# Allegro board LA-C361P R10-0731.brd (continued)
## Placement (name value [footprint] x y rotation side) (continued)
CV797  4.7U_0603_6.3V6K  [C_0603]  224.37 59.61 270 top
CV798  4.7U_0603_6.3V6K  [C_0603]  204.6 66.43 180 top
CV799  0.1U_0402_10V7K  [C_0402]  213.25 101.93 0 top
CV800  0.1U_0402_10V7K  [C_0402]  216.07 108.73 270 top
CV801  0.1U_0402_10V7K  [C_0402]  225.87 109.85 90 top
CV802  0.1U_0402_10V7K  [C_0402]  211.15 108.39 180 top
CV803  0.1U_0402_10V7K  [C_0402]  205.14 106.69 0 top
CV804  0.1U_0402_10V7K  [C_0402]  197.99 102.71 90 top
CV805  0.1U_0402_10V7K  [C_0402]  197.66 106.66 0 top
CV806  0.1U_0402_10V7K  [C_0402]  196.52 106.66 180 top
CV807  0.1U_0402_10V7K  [C_0402]  239.09 76.91 180 top
CV808  0.1U_0402_10V7K  [C_0402]  242.46 77.61 180 top
CV809  0.1U_0402_10V7K  [C_0402]  241.56 69.68 270 top
CV810  0.1U_0402_10V7K  [C_0402]  241.56 67.84 270 top
CV811  0.1U_0402_10V7K  [C_0402]  243.73 88.65 180 top
CV812  0.1U_0402_10V7K  [C_0402]  247.21 94.04 90 top
CV813  0.1U_0402_10V7K  [C_0402]  243.16 95.58 180 top
CV814  0.1U_0402_10V7K  [C_0402]  247.21 92.26 90 top
CV815  22U_0603_6.3V6M  [C_0603]  219.08 71.07 0 top
CV816  22U_0603_6.3V6M  [C_0603]  223.46 94.37 0 top
CZ4  470P_0603_50V7K  [C_0603]  310.2 33.66 180 top
CZ6  470P_0603_50V7K  [C_0603]  310.2 35.06 180 top
CZ8  10U_0603_6.3V6M  [C_0603]  307.56 32.39 180 top
CZ9  10U_0603_6.3V6M  [C_0603]  310.74 38.62 0 top
CZ11  1U_0603_10V6K  [C_0603]  55.88 6.42 90 top
CZ12  1U_0603_10V6K  [C_0603]  315.79 35.82 90 top
CZ18  1U_0402_6.3V6K  [C_0402]  58.17 6.98 90 top
CZ19  0.1U_0402_10V7K  [C_0402]  61.41 5.86 270 top
CZ20  2200P_0402_25V7K  [C_0402]  57.07 1.66 180 top
CZ26  1U_0402_6.3V6K  [C_0402]  343.35 44.55 0 bottom
CZ28  0.1U_0402_10V7K  [C_0402]  181.48 80.87 180 top
CZ29  0.1U_0402_10V7K  [C_0402]  339.35 45.3 270 bottom
CZ31  2200P_0402_25V7K  [C_0402]  340.56 43.06 180 bottom
CZ37  470P_0603_50V7K  [C_0603]  240.6 7.18 90 top
CZ39  470P_0603_50V7K  [C_0603]  241.94 7.18 90 top
CZ41  0.1U_0402_10V7K  [C_0402]  46.86 29.3 270 top
CZ43  0.1U_0402_10V7K  [C_0402]  37.85 23.17 90 top
CZ44  1U_0402_6.3V6K  [C_0402]  46.86 25.9 90 top
CZ45  0.1U_0402_10V7K  [C_0402]  237.55 8.28 270 top
CZ46  0.1U_0402_10V7K  [C_0402]  244.86 8.34 270 top
CZ47  0.1U_0402_10V7K  [C_0402]  181.23 82.18 180 bottom
CZ49  0.1U_0402_10V7K  [C_0402]  174.48 66.23 90 top
CZ53  1U_0603_10V6K  [C_0603]  181.1 14.23 90 top
CZ54  1U_0603_10V6K  [C_0603]  180.91 8.2 0 top
CZ57  2200P_0402_25V7K  [C_0402]  131.15 69.13 0 top
CZ82  0.1U_0402_10V7K  [C_0402]  184.72 83.07 270 bottom
CZ86  0.1U_0402_10V7K  [C_0402]  181.31 86.65 270 bottom
CZ88  1U_0402_6.3V6K  [C_0402]  181.23 83.12 180 bottom
CZ95  2200P_0402_25V7K  [C_0402]  228.61 61.35 180 top
CZ96  1U_0402_6.3V6K  [C_0402]  182.22 85.86 0 top
CZ97  0.1U_0402_25V6  [C_0402]  180.59 85.86 180 top
D122  -  [BAS40-04_SOT23-3]  332.8 77.15 90 top
DE2  AZ5125-02S.R7G_SOT23-3  [AZ5125-02SPR7G_SOT23-3]  345.85 110.94 90 top
DE4  -  [PESD5V0U2BT_SOT23-3]  227.59 14.11 90 bottom
DE5  -  [PESD5V0U2BT_SOT23-3]  214.33 13.75 270 top
DE7  -  [RB751S40T1G_SOD523-2]  99.23 35.41 270 top
DE8  -  [RB751S40T1G_SOD523-2]  322.71 40.59 270 top
DE9  -  [TVNST52302AB0_SOT523-3]  12.64 12.58 0 top
DE11  -  [RB751S40T1G_SOD523-2]  309.44 9.28 180 top
DH1  -  [RB751S40T1G_SOD523-2]  90.04 4.33 180 top
DI1  -  [RB751S40T1G_SOD523-2]  55.12 25.54 270 bottom
DI3  AZ5125-02S.R7G_SOT23-3  [AZ5125-02SPR7G_SOT23-3]  333.36 46.68 270 bottom
DI7  -  [AZ1045-04F_DFN2510P10E-10-9]  19.62 102.39 90 top
DI8  AZ5125-02S.R7G_SOT23-3  [AZ5125-02SPR7G_SOT23-3]  20.3 99.7 270 top
DI9  -  [AZ1045-04F_DFN2510P10E-10-9]  332.56 74.44 270 top
DI10  AZ5125-02S.R7G_SOT23-3  [AZ5125-02SPR7G_SOT23-3]  330.58 68.18 180 bottom
DI11  -  [RB751S40T1G_SOD523-2]  313.56 31.69 90 bottom
DI12  BAT54CW-7-F_SOT323-3~D  [BAT54CW-7-F_SOT323-3]  323.03 43.38 180 top
DL1  AZ5125-02S.R7G_SOT23-3  [AZ5125-02SPR7G_SOT23-3]  344.27 114.94 270 top
DN1  -  [RB751S40T1G_SOD523-2]  329.95 80.59 90 bottom
DN2  -  [RB751S40T1G_SOD523-2]  328.8 80.59 90 bottom
DN3  BAT54CW-7-F_SOT323-3~D  [BAT54CW-7-F_SOT323-3]  338.2 103.96 270 top
DT10  AZ4024-02S_SOT23-3~D  [PESD24VS2UT_SOT23-3]  3.68 30.08 0 top
DT12  -  [ESD108-B1-CSP0201_WLL-2-1-2]  11.18 68.78 90 top
DT13  -  [ESD108-B1-CSP0201_WLL-2-1-2]  11.18 68.12 270 top
DT14  -  [ESD108-B1-CSP0201_WLL-2-1-2]  9.74 66.95 0 top
DT15  -  [ESD108-B1-CSP0201_WLL-2-1-2]  11.18 66.62 90 top
DT16  -  [ESD108-B1-CSP0201_WLL-2-1-2]  11.18 65.96 270 top
DT17  -  [ESD108-B1-CSP0201_WLL-2-1-2]  9.46 64.65 0 top
DT18  -  [ESD108-B1-CSP0201_WLL-2-1-2]  11.18 63.93 90 top
DT19  -  [ESD108-B1-CSP0201_WLL-2-1-2]  11.18 63.17 270 top
DT20  -  [ESD108-B1-CSP0201_WLL-2-1-2]  9.4 70.68 90 bottom
DT21  -  [ESD108-B1-CSP0201_WLL-2-1-2]  9.4 69.92 270 bottom
DT22  -  [ESD108-B1-CSP0201_WLL-2-1-2]  5.53 71.58 0 top
DT23  -  [ESD108-B1-CSP0201_WLL-2-1-2]  11.18 73.1 90 top
DT24  -  [ESD108-B1-CSP0201_WLL-2-1-2]  11.18 72.44 270 top
DT25  -  [ESD108-B1-CSP0201_WLL-2-1-2]  6.42 59.83 0 top
DT26  -  [ESD108-B1-CSP0201_WLL-2-1-2]  10.1 61.86 0 bottom
DT27  -  [ESD108-B1-CSP0201_WLL-2-1-2]  9.34 61.86 180 bottom
DT28  -  [RB751S40T1G_SOD523-2]  9.2 67.98 0 bottom
DT29  -  [RB751S40T1G_SOD523-2]  24.83 43.57 180 top
DV1  BAT54CW-7-F_SOT323-3~D  [BAT54CW-7-F_SOT323-3]  53.32 26.86 0 top
DV2  BAT54CW-7-F_SOT323-3~D  [BAT54CW-7-F_SOT323-3]  50.29 26.87 0 top
DV4  -  [AZ1045-04F_DFN2510P10E-10-9]  15.06 86.35 270 top
DV5  -  [AZ1045-04F_DFN2510P10E-10-9]  15.93 80.29 90 top
DV7  BAT54CW-7-F_SOT323-3~D  [BAT54CW-7-F_SOT323-3]  36.39 28.93 180 top
DV8  BAT54AW-7-F_SOT323-3  [BAT54CW-7-F_SOT323-3]  200.28 56.23 0 top
DV9  BAT54CW-7-F_SOT323-3~D  [BAT54CW-7-F_SOT323-3]  209.3 58.18 0 bottom
DV10  -  [RB751S40T1G_SOD523-2]  213.27 58.92 0 top
DV11  -  [RB751S40T1G_SOD523-2]  213.27 60.07 0 top
DV12  -  [IP4223CZ6_SO6-6]  58.17 25.19 0 bottom
DZ1  BAT54AW-7-F_SOT323-3  [BAT54CW-7-F_SOT323-3]  168.4 10.36 180 bottom
FD1  FIDUCAL  [FIDUCIAL_C40M80]  343.22 6.99 0 top
FD2  FIDUCIAL  [FIDUCIAL_C40M80]  22.87 73.29 0 top
FD3  FIDUCAL  [FIDUCIAL_C40M80]  23.43 109.67 180 bottom
FD4  FIDUCIAL  [FIDUCIAL_C40M80]  343.22 6.99 180 bottom
H1  -  [H_2P3]  248.4 1.6 0 top
H2  -  [H_2P3]  29 105.5 0 top
H5  -  [H_3P2]  229.4 106.27 0 top
H6  -  [H_3P2]  235.99 56.73 0 top
H9  -  [H_2P5]  231 118.5 0 top
H10  -  [H_2P5]  4 8 0 top
H11  -  [H_2P1N]  4 11.7 0 top
H12  -  [H_6P0N]  9.1 28.7 0 top
H13  -  [H_3P9]  138.92 103.09 0 top
H16  -  [H_3P9]  187.78 92 0 top
H17  -  [H_2P1X2P5N]  27.61 109.84 346 top
H18  -  [EMIST_SUL-12A2M_1P]  10.45 111.9 0 top
H19  -  [EMIST_SUL-12A2M_1P]  20.38 111.9 0 top
H20  -  [EMIST_SUL-12A2M_1P]  11.5 111.9 180 bottom
H21  -  [EMIST_SUL-12A2M_1P]  18 103.2 270 bottom
H22  -  [EMIST_SUL-12A2M_1P]  25.45 103.25 90 top
H23  -  [EMIST_SUL-12A2M_1P]  102.85 60.66 270 bottom
H24  -  [EMIST_SUL-12A2M_1P]  102.87 85.68 270 bottom
H25  -  [EMIST_SUL-12A2M_1P]  113 54.55 180 bottom
H26  -  [EMIST_SUL-12A2M_1P]  341.44 81.61 0 top
H27  -  [EMIST_SUL-12A2M_1P]  331.55 81.61 0 top
H28  -  [EMIST_SUL-12A2M_1P]  326.7 72.95 90 top
H29  -  [EMIST_SUL-12A2M_1P]  331.57 64.3 180 top
H30  -  [EMIST_SUL-12A2M_1P]  341.47 64.3 180 top
H31  -  [EMIST_SUL-12A2M_1P]  334 72.95 270 bottom
H32  -  [EMIST_SUL-12A2M_1P]  340.5 64.3 180 bottom
H33  -  [EMIST_SUL-12A2M_1P]  340.5 81.6 180 bottom
H34  -  [EMIST_SUL-12A2M_1P]  11.5 94.6 180 bottom
H35  -  [EMIST_SUL-12A2M_1P]  10.47 94.6 0 top
H36  -  [EMIST_SUL-12A2M_1P]  20.42 94.6 0 top
H37  -  [H_3P0]  3.75 1.14 0 top
H38  -  [H_3P0]  3.75 23.64 0 top
H39  -  [H_2P5]  121 118.5 0 top
H40  -  [H_2P5]  348 3 0 top
H41  -  [H_2P8]  208.3 4.52 0 top
H42  -  [H_2P8]  143.7 4.52 0 top
H43  -  [H_2P3]  323.35 65 0 top
H45  -  [H_3P9]  187.78 57.33 180 top
H46  -  [H_3P9]  127.75 60.02 0 top
H47  -  [H_6P0N]  342.9 28.7 0 top
H48  -  [H_4P1]  344 13.3 0 top
H49  -  [H_2P3]  343.2 120 0 top
H50  -  [CLIP_C6]  337.76 117.45 180 bottom
H51  -  [CLIP_C5P5]  61.6 13.65 180 bottom
H52  -  [EMIST_SUL-12A2M_1P]  203.16 117 270 bottom
H53  -  [EMIST_SUL-12A2M_1P]  184.75 120.55 0 bottom
H54  -  [CLIP_C5P5]  259.65 39.25 180 bottom
H55  -  [CLIP_C5P5]  97.2 43.45 180 bottom
H56  -  [EMIST_SUL-12A2M_1P]  159.75 120.55 180 bottom
H57  -  [EMIST_SUL-12A2M_1P]  134.75 120.55 180 bottom
H58  -  [EMIST_SUL-12A2M_1P]  125.76 117 270 bottom
H59  -  [H_2P9X2P1N]  348 6.8 0 top
JAPS  ACES_50506-01841-P01  [ACES_50506-01841-P01_18P]  178.62 7.44 180 bottom
JAUDIO  E-T_1133K-R30C-01L~D  [E-T_1133K-R30C-01L_30P]  4 19.93 0 top
JCR  T-SOL_156-1001302601_NR  [T-SOL_156-1001302601_19P_NR-T]  327.55 56.05 90 top
JDEG1  HB_A531015-SCHR21  [HB_A531015-SCHR21_10P]  311.11 31.25 180 bottom
JDIMM1  BELLW_SD-80886-1021  [BELLW_SD-80886-1021_260P-T]  107.37 26.35 180 bottom
JDIMM2  BELLW_SD-80886-1021  [BELLW_SD-80886-1021_260P-T]  183.68 26.35 180 bottom
JEDP1  ACES_59003-04006-001  [ACES_59003-04006-001_40P]  71.55 32.82 0 bottom
JFAN1  ACES_50224-00401-001  [ACES_50224-00401-001_4P]  98.48 35.2 90 bottom
JFAN2  ACES_50224-00401-001  [ACES_50224-00401-001_4P]  320.5 39.62 0 bottom
JHDD  J-L_UCNR2234B020-0  [J-L_UCNR2234B020-0_20P]  231.36 10.48 0 bottom
JHDMI1  ACON_HMRB9-AK120C  [ACON_HMRB9-AK120C_19P]  11.77 79.43 270 top
JKB  E-T_6710K-Y15M-31L  [E-T_6710K-Y15M-31L_15P]  163.27 10.32 180 bottom
JLPDE1  HB_A531015-SCHR21  [HB_A531015-SCHR21_10P]  300.7 31.25 180 bottom
JNGFF1  CONCR_213AAAA32FA  [CONCR_213AAAA32FA_67P]  328.55 83.92 0 bottom
JNGFF2  CONCR_213MAAA32FA  [CONCR_213MAAA32FA_67P-T]  260.48 22.54 270 bottom
JRTC  E&T_3806K-F02N-03R  [E-T_3806K-F02N-03R_2P]  326.75 104.25 0 top
JTAG1  @SHORT PADS~D  [SHORTPADS]  297.44 25.54 0 top
JTP  ACES_51524-0080N-001  [ACES_51524-0080N-001_8P]  223.4 13 180 bottom
JTS  ACES_50208-00601-P01  [ACES_50208-00601-P01_6P]  333.79 50.6 0 bottom
JUART  ACES_50207-00471-P01  [ACES_50207-00471-P01_4P-T]  103.47 48.95 270 bottom
JUSB1  TAIWI_USB019-107CRL-TWD  [TAIWI_USB019-107CRL-TWD_10P-T]  14.68 106.7 270 top
JUSB2  TAIWI_USB019-107CRL-TWD  [TAIWI_USB019-107CRL-TWD_10P-T]  337.32 69.45 90 top
JUSBC1  JAE_DX07S024XJ2  [JAE_DX07S024XJ2_24P-T]  7.86 68.56 270 top
JXDP  SAMTE_BSH-030-01-L-D-A  [SAMTE_BSH-030-01-L-D-A_60P]  128.19 85.51 90 top
LED1  27-21-T3D-CP1Q2B16Y-3C_WHITE  [LED_LTW-270TLA_2P]  349 108.09 270 top
LED2  27-21-T3D-CP1Q2B16Y-3C_WHITE  [LED_LTW-270TLA_2P]  349 104.49 270 top
LED3  27-21-T3D-CP1Q2B16Y-3C_WHITE  [LED_LTW-270TLA_2P]  349 100.89 270 top
LED4  27-21-T3D-CP1Q2B16Y-3C_WHITE  [LED_LTW-270TLA_2P]  349 97.29 270 top
LED5  27-21-T3D-CP1Q2B16Y-3C_WHITE  [LED_LTW-270TLA_2P]  349 93.69 270 top
LED6  HT-F196BP5_WHITE  [LED_HT-F196BP5_2P]  335.21 119.71 180 top
LH1  BLM15PX221SN1D_2P  [MURAT_BLM15PX221SN1D_2P]  113.92 8.98 90 top
LH2  BLM15PX221SN1D_2P  [MURAT_BLM15PX221SN1D_2P]  107.82 13.39 270 top
LI1  MCM1012B900F06BP_4P  [INPAQ_MCM1012B900F06BP_4P]  328.09 44.97 90 bottom
LI2  MCM1012B900F06BP_4P  [INPAQ_MCM1012B900F06BP_4P]  328.09 67.37 90 bottom
LI5  MCM1012B900F06BP_4P  [INPAQ_MCM1012B900F06BP_4P]  21.85 96.78 180 top
LN1  MCM1012B900F06BP_4P  [INPAQ_MCM1012B900F06BP_4P]  325.15 81.09 0 bottom
LT1  0.6UH_XFL4012-601MEC_20%  [COILC_XFL4012-601MEC_2P]  23.5 49.37 180 bottom
LT11  HCB2012KF-121T50_2P  [TAI-T_HCB2012KF-121T50_2P]  3.77 33.39 270 bottom
LT12  CMMI21T-900Y-N_4P  [CHILI_CMMI21T-900Y-N_4P]  13.91 65.85 90 top
LT13  CMMI21T-900Y-N_4P  [CHILI_CMMI21T-900Y-N_4P]  13.93 72.33 90 top
LT14  LQM18PN1R0MFHD_2P  [CHILI_PBY160808T-300Y-N_2P]  18.29 40.76 90 bottom
LV2  PBY160808T-301Y-N_2P  [CHILI_PBY160808T-300Y-N_2P]  205.04 63.5 270 top
LV3  BLM15PX121SN1D_2P  [MURAT_BLM15PX121SN1D_2P]  196.67 92.46 0 top
LV14  BLM15PD300SN1D_2P  [MURAT_BLM15PX330SN1D_2P]  209.93 66.42 270 top
LV21  HCB1608KF-300T20  [MURAT_BLM18PG300SN1D_2P]  230.25 97.04 270 top
LV22  MCM1012B900F06BP_4P  [INPAQ_MCM1012B900F06BP_4P]  58.29 19.44 90 bottom
NOREF  -  []  187.52 13.1 0 top
NOREF#2  -  []  344 13.3 0 top
NOREF#3  -  []  348 3 270 top
NOREF#4  -  []  229.4 106.27 0 top
NOREF#5  -  []  121 118.5 0 top
NOREF#6  -  []  143.7 4.52 270 top
NOREF#7  -  []  4 8 270 top
NOREF#8  -  []  208.3 4.52 270 top
NOREF#9  -  []  127.75 60.02 0 top
NOREF#10  -  []  154.21 31.47 0 top
NOREF#11  -  []  158.26 -41.93 0 top
NOREF#12  -  []  187.78 92 0 top
NOREF#13  -  []  53.85 127.14 0 top
NOREF#14  -  []  231 118.5 0 top
NOREF#15  -  []  235.99 56.73 0 top
NOREF#16  -  []  235.5 -67.62 0 top
NOREF#17  -  []  3.75 23.64 90 top
NOREF#18  -  []  187.78 57.33 0 top
NOREF#19  -  []  138.92 103.09 0 top
NOREF#20  -  []  136.37 -65.41 0 top
NOREF#21  -  []  231 118.5 0 top
NOREF#22  -  []  231 118.5 0 top
NOREF#23  -  []  83.48 11.32 180 bottom
NOREF#24  -  []  68.28 70.27 180 bottom
NOREF#25  -  []  234.19 34.93 90 bottom
NOREF#26  -  []  218.19 34.3 90 bottom
NOREF#27  -  []  148.46 46.11 180 bottom
NOREF#28  -  []  206.38 34.43 90 bottom
PC106  0.1U_0402_25V6  [C_0402]  26.26 75.71 0 bottom
PC107  100P_0402_50V8J  [C_0402]  22.23 24.01 180 bottom
PC108  0.01UF_0402_25V7K  [C_0402]  22.23 23.12 180 bottom
PC109  1000P_0402_50V7K  [C_0402]  27.56 17.7 0 top
PC110  100P_0402_50V8J  [C_0402]  27.56 16.81 0 top
PC111  0.22U_0603_25V7K  [C_0603]  32.39 17.03 180 top
PC112  0.1U_0402_25V6  [C_0402]  28.07 14.92 90 top
PC113  .1U_0402_16V7K  [C_0402]  60.08 17.6 180 bottom
PC114  0.1U_0402_25V6  [C_0402]  21.21 88.32 90 bottom
PC115  0.1U_0402_25V6  [C_0402]  22.1 88.32 90 bottom
PC200  0.022U_0603_50V7K  [C_0603]  20.63 87.27 180 bottom
PC201  100P_0402_50V8J  [C_0402]  26.29 72.98 0 bottom
PC202  0.1U_0402_25V6  [C_0402]  26.75 65.07 0 bottom
PC203  1000P_0402_50V7K  [C_0402]  26.75 65.96 0 bottom
PC204  100P_0402_50V8J  [C_0402]  26.75 64.19 0 bottom
PC205  1000P_0402_50V7K  [C_0402]  26.28 73.9 0 bottom
PC206  15P_0402_50V8J  [C_0402]  26.28 74.8 0 bottom
PC207  0.022U_0603_50V7K  [C_0603]  26.54 13.28 180 top
PC208  0.022U_0603_50V7K  [C_0603]  25.34 57.16 0 bottom
PC209  0.1U_0603_25V7K~D  [C_0603]  16.64 50.94 0 bottom
PC210  220P_0402_50V7K  [C_0402]  28.7 31.2 270 bottom
PC211  1000P_0402_50V7K  [C_0402]  28.88 31.25 0 top
PC212  100P_0402_50V8J  [C_0402]  22.24 25.79 180 bottom
PC213  1200P_0402_50V7K  [C_0402]  22.57 28.84 180 bottom
PC214  220P_0402_50V7K  [C_0402]  9.4 19.5 0 bottom
PC215  220P_0402_50V7K  [C_0402]  19.51 21.01 180 bottom
PC216  1P_0402_50V8  [C_0402]  10.31 20.41 180 bottom
PC217  1200P_0402_50V7K  [C_0402]  18.59 21.98 0 bottom
PC218  1U_0402_16V6K  [C_0402]  24.96 17.01 90 top
PC219  1U_0603_25V6  [C_0603]  27.43 18.8 0 top
PC220  0.022U_0603_50V7K  [C_0603]  21.04 64.18 180 bottom
PC221  0.022U_0603_50V7K  [C_0603]  18.86 59.33 180 bottom
PC222  0.022U_0603_50V7K  [C_0603]  23.75 65.79 0 top
PC223  0.01U_0402_25V7K  [C_0402]  34.6 32.83 0 top
PC224  0.01U_0402_25V7K  [C_0402]  28.88 29.47 0 top
PC225  0.1U_0402_10V7K  [C_0402]  10.21 12.52 0 top
PC288  0.022U_0603_50V7K  [C_0603]  27.05 59.13 270 top
PC289  0.022U_0603_50V7K  [C_0603]  23.75 64.52 0 top
PC306  2200P_0402_50V7K  [C_0402]  49.48 11.22 0 bottom
PC307  22U_0805_25V6M  [C_0805]  51.36 6.56 270 bottom
PC308  22U_0805_25V6M  [C_0805]  51.36 6.59 270 top
PC309  22U_0805_25V6M  [C_0805]  49.59 6.57 270 top
PC310  22U_0805_25V6M  [C_0805]  49.61 6.57 270 bottom
PC311  1U_0603_25V6K  [C_0603]  54.48 15.76 270 bottom
PC312  100U_D_20VM_R55M  [C_D]  39.75 18.8 180 bottom
PC313  0.1U_0402_25V6  [C_0402]  53.09 12.9 180 top
PC314  0.1U_0402_25V6  [C_0402]  53.28 14.54 90 bottom
PC315  10U_0805_25V6K  [C_0805]  43.05 21.88 270 top
PC316  10U_0805_25V6K  [C_0805]  44.83 21.88 270 top
PC317  10U_0805_25V6K  [C_0805]  43.05 21.88 270 bottom
PC318  10U_0805_25V6K  [C_0805]  44.83 21.88 270 bottom
PC319  1U_0805_25V6K  [C_0805]  51.25 14.74 180 top
PC320  1U_0603_10V6K  [C_0603]  50.8 18.86 180 top
PC321  0.047U_0603_25V7M  [C_0603]  49.4 16.26 0 top
PC322  0.1U_0402_25V6  [C_0402]  56.01 11.76 90 top
PC323  0.1U_0603_25V7K  [C_0603]  30.01 18.68 0 top
PC324  10U_0805_25V6K  [C_0805]  29.77 20.25 0 bottom
PC325  10U_0805_25V6K  [C_0805]  29.88 20.25 0 top
PC326  10U_0805_25V6K  [C_0805]  29.78 18.54 0 bottom
PC327  100P_0402_50V8J  [C_0402]  57.79 12.65 270 top
PC328  100P_0402_50V8J  [C_0402]  57.8 15.63 180 bottom
PC329  1000P_0603_50V7K  [C_0603]  33.08 2.49 0 top
PC330  0.1U_0402_25V6  [C_0402]  53.28 23.07 270 top
PC331  0.1U_0402_25V6  [C_0402]  53.39 20.77 0 top
PC332  0.1U_0402_25V6  [C_0402]  54.23 22.16 90 top
PC333  1U_0603_25V6K  [C_0603]  56.26 22.61 270 top
PC334  0.1U_0402_25V6  [C_0402]  49.51 11.22 0 top
PC335  4.7U_0603_6.3V6M  [C_0603]  348.04 25.41 90 top
PC336  22U_0805_25V6M  [C_0805]  53.1 6.6 270 bottom
PC337  22U_0805_25V6M  [C_0805]  53.1 6.61 270 top
PC400  4.7U_0603_6.3V6M  [C_0603]  347.96 20.91 0 top
PC401  100P_0402_50V8J  [C_0402]  348.88 22.87 180 bottom
PC402  100P_0402_50V8J  [C_0402]  347.9 19.82 0 bottom
PC403  15P_0402_50V8J  [C_0402]  324.74 18.68 90 top
PC404  0.1U_0402_25V6  [C_0402]  325.63 18.68 90 top
PC405  2200P_0402_50V7K  [C_0402]  323.85 18.68 90 top
PC406  10U_0805_25V6K  [C_0805]  328.74 18.42 90 top
PC407  0.1U_0402_25V6  [C_0402]  322.07 18.68 90 top
PC408  2200P_0402_50V7K  [C_0402]  322.96 18.68 90 top
PC409  10U_0805_25V6K  [C_0805]  326.96 18.42 90 top
PC410  0.1U_0603_50V7K  [C_0603]  339.85 24.08 0 top
PC411  0.1U_0603_50V7K  [C_0603]  344.23 17.22 0 top
PC412  150U_B2_6.3VM_R35M  [C_B2]  327.72 24.39 90 top
PC413  150U_B2_6.3VM_R35M  [C_B2]  326.39 4.34 270 top
PC414  680P_0603_50V7K  [C_0603]  335.84 32.27 270 top
PC415  .1U_0402_16V7K  [C_0402]  338.14 19.07 270 top
PC416  .1U_0402_16V7K  [C_0402]  333.38 17.15 0 top
PC417  680P_0603_50V7K  [C_0603]  339.03 14.74 90 top
PC418  0.1U_0402_25V6  [C_0402]  340.58 20.98 180 top
PC419  4.7U_0603_6.3V6M  [C_0603]  340.82 19.83 180 top
PC420  100U_D_20VM_R55M  [C_D]  323.47 15.76 270 top
PC500  0.22U_0402_10V6K  [C_0402]  131.57 3.18 270 top
PC501  680P_0603_50V7K  [C_0603]  130.56 8.77 0 bottom
PC502  2200P_0402_50V7K  [C_0402]  135.33 7.43 270 bottom
PC503  0.1U_0402_25V6  [C_0402]  135.33 7.43 270 top
PC504  10U_0805_25V6K  [C_0805]  135.22 8.77 180 top
PC505  0.1U_0402_25V6  [C_0402]  132.09 5.98 180 top
PC506  10U_0805_25V6K  [C_0805]  135.22 8.77 180 bottom
PC507  220P_0402_50V8J  [C_0402]  134.79 2.23 90 bottom
PC508  22U_0805_6.3VAM  [C_0805]  119 6.42 270 top
PC509  22U_0805_6.3VAM  [C_0805]  120.78 6.38 270 bottom
PC510  22U_0805_6.3VAM  [C_0805]  120.78 6.42 270 top
PC511  22U_0805_6.3VAM  [C_0805]  119 6.38 270 bottom
PC512  4.7U_0603_6.3V6K  [C_0603]  135.64 4.2 0 bottom
PC513  4.7U_0603_6.3V6K  [C_0603]  135.64 5.47 0 bottom
PC600  0.22U_0603_16V7K  [C_0603]  284.54 27.38 180 bottom
PC601  10U_0805_25V6K  [C_0805]  276.29 30.9 270 bottom
PC602  10U_0805_25V6K  [C_0805]  275.97 30.9 270 top
PC603  0.1U_0402_25V6  [C_0402]  274.58 30.5 270 top
PC604  2200P_0402_50V7K  [C_0402]  274.96 30.5 270 bottom
PC605  10U_0805_6.3V6M  [C_0805]  284.35 30.62 90 top
PC606  10U_0805_6.3V6M  [C_0805]  282.58 30.62 90 top
PC607  1U_0603_10V6K  [C_0603]  287.34 25.41 0 bottom
PC608  330U_D1_2VY_R9M  [C_D1]  258.26 28 90 bottom
PC609  .1U_0402_16V7K  [C_0402]  288.29 32.65 180 bottom
PC610  1U_0603_10V6K  [C_0603]  290.13 26.68 270 bottom
PC611  680P_0603_50V7K  [C_0603]  265.43 27.44 270 bottom
PC612  22P_0402_50V8J  [C_0402]  291.85 31.19 90 bottom
PC613  0.1U_0402_10V7K  [C_0402]  291.83 28.46 0 top
PC614  0.1U_0402_10V7K  [C_0402]  291.83 30.23 0 bottom
PC700  1U_0603_10V7K  [C_0603]  243.84 45.92 90 top
PC701  4700P_0402_25V7K  [C_0402]  244.98 46.35 90 top
PC702  47P_0402_50V8J  [C_0402]  241.87 47.52 270 top
PC703  .1U_0402_16V7K  [C_0402]  240.98 47.52 270 top
PC704  2200P_0402_50V7K  [C_0402]  242.76 47.52 270 top
PC705  4.7U_0603_25V6K  [C_0603]  239.46 48.13 90 top
PC706  4.7U_0603_25V6K  [C_0603]  235.9 48.13 90 top
PC707  4.7U_0603_25V6K  [C_0603]  237.68 48.13 90 top
PC708  .1U_0402_16V7K  [C_0402]  248.54 50.3 90 top
PC709  33P_0603_50V8J  [C_0603]  235.59 50.95 90 top
PC710  22U_0805_6.3VAM  [C_0805]  247.17 61.6 180 bottom
PC711  22U_0805_6.3VAM  [C_0805]  247.17 61.6 180 top
PC712  22U_0805_6.3VAM  [C_0805]  247.17 63.38 180 bottom
PC713  .1U_0603_25V7K  [C_0603]  244.35 54.43 90 top
PC755  22U_0805_6.3VAM  [C_0805]  247.61 58.17 180 top
PC800  0.22U_0402_10V6K  [C_0402]  109.03 64.51 90 top
PC801  680P_0603_50V7K  [C_0603]  109.98 58.43 270 bottom
PC802  0.1U_0402_25V6  [C_0402]  107.44 58.73 0 bottom
PC803  2200P_0402_50V7K  [C_0402]  107.44 58.73 0 top
PC804  10U_0805_25V6K  [C_0805]  107.04 57.41 0 bottom
PC805  0.1U_0603_25V7K  [C_0603]  108.4 61.03 0 top
PC806  10U_0805_25V6K  [C_0805]  107.04 57.41 0 top
PC807  220P_0402_50V8J  [C_0402]  106.17 65.43 270 top
PC808  22U_0805_6.3VAM  [C_0805]  116.33 60.7 270 top
PC809  22U_0805_6.3VAM  [C_0805]  118.11 60.7 270 top
PC810  22U_0805_6.3VAM  [C_0805]  118.11 60.6 270 bottom
PC811  22U_0805_6.3VAM  [C_0805]  116.33 60.58 270 bottom
PC812  4.7U_0603_6.3V6K  [C_0603]  105.73 62.11 180 bottom
PC813  4.7U_0603_6.3V6K  [C_0603]  105.03 64.08 90 bottom
PC900  0.1U_0402_25V6  [C_0402]  220.16 54.17 90 top
PC901  680P_0603_50V7K  [C_0603]  213.3 54.3 180 top
PC902  0.1U_0402_25V6  [C_0402]  211.01 50.99 90 top
PC903  10U_0805_25V6K  [C_0805]  215.08 50.47 90 top
PC904  10U_0805_25V6K  [C_0805]  213.3 50.47 90 top
PC905  2200P_0402_50V7K  [C_0402]  211.9 50.99 90 top
PC906  0.1U_0603_25V7K  [C_0603]  218.82 46.94 90 top
PC907  220P_0402_50V8J  [C_0402]  222.26 49.03 180 top
PC908  22U_0805_6.3VAM  [C_0805]  208.73 55.98 270 top
PC909  22U_0805_6.3VAM  [C_0805]  208.92 55.98 270 bottom
PC910  22U_0805_6.3VAM  [C_0805]  210.5 55.98 270 top
PC911  22U_0805_6.3VAM  [C_0805]  210.71 55.98 270 bottom
PC912  4.7U_0603_6.3V6K  [C_0603]  221.23 47.95 0 top
PC913  4.7U_0603_6.3V6K  [C_0603]  217.55 48.33 270 top
PC1000  0.1U_0402_25V6  [C_0402]  163.64 106.82 180 bottom
PC1001  10U_0805_25VAK  [C_0805]  176.06 105.23 0 top
PC1002  10U_0805_25VAK  [C_0805]  176.06 105.23 0 bottom
PC1003  1U_0402_6.3VAK  [C_0402]  211.07 74.37 0 top
PC1004  1U_0402_6.3VAK  [C_0402]  210.21 74.37 180 top
PC1005  47P_0402_50V8J  [C_0402]  176.21 115.13 0 top
PC1006  0.1U_0402_25V6  [C_0402]  176.21 116.09 0 top
PC1007  2200P_0402_50V7K  [C_0402]  176.21 114.18 0 top
PC1008  .01U_0402_16V7K  [C_0402]  163.64 105.86 180 top
PC1009  2700P_0402_50V7K  [C_0402]  163.7 102.42 90 bottom
PC1010  0.1U_0603_50V7K  [C_0603]  170.73 102.5 90 bottom
PC1011  0.01UF_0402_25V7K  [C_0402]  167.32 103.32 270 bottom
PC1012  4.7U_0603_6.3VAK  [C_0603]  208.87 83.39 0 top
PC1013  4.7U_0603_6.3VAK  [C_0603]  213.81 75.57 0 top
PC1014  4.7U_0603_6.3VAK  [C_0603]  210.25 82.11 180 top
PC1015  4.7U_0603_6.3VAK  [C_0603]  212.74 82.08 180 top
PC1016  4.7U_0603_6.3VAK  [C_0603]  210.25 79.64 180 top
PC1017  4.7U_0603_6.3VAK  [C_0603]  211.01 73.23 270 top
PC1018  4.7U_0603_6.3VAK  [C_0603]  209.82 73.23 270 top
PC1019  4.7U_0603_6.3VAK  [C_0603]  211.33 79.64 0 top
PC1020  4.7U_0603_6.3VAK  [C_0603]  211.28 75.57 0 top
PC1021  4.7U_0603_6.3VAK  [C_0603]  210.25 78.37 180 top
PC1022  330U_B2_2.5VM_R9M  [C_B2]  181.48 95.51 0 bottom
PC1023  330U_B2_2.5VM_R9M  [C_B2]  194.02 117.99 180 bottom
PC1024  330U_B2_2.5VM_R9M  [C_B2]  194.02 114.79 180 bottom
PC1025  47P_0603_50V8J  [C_0603]  179.13 108.66 180 top
PC1027  4.7U_0603_6.3VAK  [C_0603]  211.33 78.37 0 top
PC1028  4.7U_0603_6.3VAK  [C_0603]  210.25 75.64 180 top
PC1029  .01U_0402_16V7K  [C_0402]  162.75 107.77 0 top
PC1033  4.7U_0603_6.3VAK  [C_0603]  212.23 73.23 270 top
PC1034  4.7U_0603_6.3VAK  [C_0603]  213.5 73.23 270 top
PC1035  4.7U_0603_6.3VAK  [C_0603]  214.77 73.23 270 top
PC1036  33P_0402_50V8J  [C_0402]  162.67 109.17 0 bottom
PC1037  10U_0805_25VAK  [C_0805]  175.55 112.72 0 top
PC1038  10U_0805_25VAK  [C_0805]  175.55 112.72 0 bottom
PC1039  47P_0402_50V8J  [C_0402]  175.83 106.69 0 top
PC1040  0.1U_0402_25V6  [C_0402]  175.83 107.64 0 top
PC1041  2200P_0402_50V7K  [C_0402]  175.83 108.59 0 top
PC1042  .1U_0603_25V7K  [C_0603]  172.09 107.9 0 bottom
PC1043  1U_0402_6.3VAK  [C_0402]  216.61 75.89 0 top
PC1044  1U_0402_6.3VAK  [C_0402]  215.84 73.16 0 top
PC1045  .01U_0402_16V7K  [C_0402]  162.69 110.99 0 bottom
PC1046  0.01UF_0402_25V7K  [C_0402]  162.69 111.9 0 bottom
PC1047  0.1U_0603_50V7K  [C_0603]  170.82 112.72 270 bottom
PC1048  22U_0603_6.3V6M  [C_0603]  216.35 79.57 0 top
PC1049  4.7U_0603_6.3V6K  [C_0603]  219.08 82.27 270 top
PC1050  4.7U_0805_6.3V6K  [C_0805]  181.17 98.69 180 top
PC1051  4.7U_0603_6.3V6K  [C_0603]  217.79 83.7 180 top
PC1052  22U_0603_6.3V6M  [C_0603]  216.31 78.36 0 top
PC1053  4.7U_0805_6.3V6K  [C_0805]  181.17 96.91 180 top
PC1054  4.7U_0805_6.3V6K  [C_0805]  219.21 75.64 90 top
PC1055  47P_0603_50V8J  [C_0603]  179.64 115.9 180 top
PC1056  15P_0402_50V8J  [C_0402]  194.93 117.8 0 top
PC1057  15P_0402_50V8J  [C_0402]  194.93 116.85 0 top
PC1058  15P_0402_50V8J  [C_0402]  194.93 115.9 0 top
PC1059  15P_0402_50V8J  [C_0402]  194.93 114.94 0 top
PC1060  10U_0805_25VAK  [C_0805]  175.43 96.91 0 top
PC1061  10U_0805_25VAK  [C_0805]  175.43 96.72 0 bottom
PC1062  1U_0402_6.3VAK  [C_0402]  213.11 83.59 90 top
PC1063  1U_0402_6.3VAK  [C_0402]  213.79 74.16 180 top
PC1064  47P_0402_50V8J  [C_0402]  175.9 98.24 0 top
PC1065  0.1U_0402_25V6  [C_0402]  175.83 99.26 0 top
PC1066  2200P_0402_50V7K  [C_0402]  175.9 98.05 0 bottom
PC1067  0.1U_0603_50V7K  [C_0603]  172.34 101.67 270 bottom
PC1068  47P_0603_50V8J  [C_0603]  179.07 100.97 180 top
PC1069  1U_0402_6.3VAK  [C_0402]  194.95 118.75 0 top
PC1070  1U_0402_6.3VAK  [C_0402]  214.9 74.19 0 top
PC1071  22U_0603_6.3V6M  [C_0603]  217.74 82.11 180 top
PC1072  22U_0603_6.3V6M  [C_0603]  216.27 80.84 0 top
PC1073  22U_0603_6.3V6M  [C_0603]  210.25 80.84 180 top
PC1074  22U_0603_6.3V6M  [C_0603]  211.33 80.84 0 top
PC1075  22U_0603_6.3V6M  [C_0603]  213.75 82.11 0 top
PC1076  22U_0603_6.3V6M  [C_0603]  208.41 73.22 270 top
PC1077  22U_0603_6.3V6M  [C_0603]  216.32 77.14 0 top
PC1079  22U_0603_6.3V6M  [C_0603]  215.08 78.18 180 top
PC1080  22U_0603_6.3V6M  [C_0603]  215.09 79.45 180 top
PC1081  22U_0603_6.3V6M  [C_0603]  213.81 76.91 0 top
PC1082  22U_0603_6.3V6M  [C_0603]  211.33 76.84 0 top
PC1083  22U_0603_6.3V6M  [C_0603]  210.25 76.84 180 top
PC1100  4700P_0402_25V7K  [C_0402]  111.1 109.99 0 top
PC1101  1U_0402_16V6K  [C_0402]  117.54 111.2 90 top
PC1102  0.22U_0603_16V7K  [C_0603]  118.62 111.04 90 top
PC1103  330P_0402_50V7K  [C_0402]  111.1 109.04 0 top
PC1104  47P_0402_50V8J  [C_0402]  111.1 107.13 0 top
PC1105  8200P_0402_25V7K  [C_0402]  108.78 106.24 0 bottom
PC1106  680P_0402_50V7K  [C_0402]  108.78 104.47 90 top
PC1107  0.01UF_0402_25V7K  [C_0402]  117.54 100.47 270 top
PC1108  2200P_0402_50V7K  [C_0402]  123.47 109.8 180 top
PC1109  0.01UF_0402_25V7K  [C_0402]  112.03 105.86 180 top
PC1110  .1U_0402_16V7K  [C_0402]  124.84 108.02 0 top
PC1111  .047U_0402_16V7K  [C_0402]  123.41 109.03 180 bottom
PC1112  0.033U_0402_16V7K  [C_0402]  111.63 103.96 180 top
PC1113  2200P_0402_50V7K  [C_0402]  111.13 106.24 0 bottom
PC1114  330P_0402_50V7K  [C_0402]  122.56 105.23 0 top
PC1115  68P_0402_50V8J  [C_0402]  122.56 106.18 0 top
PC1116  680P_0402_50V7K  [C_0402]  124.83 107.13 0 top
PC1117  2200P_0402_50V7K  [C_0402]  122.56 104.34 0 bottom
PC1118  220P_0402_50V8J  [C_0402]  124.89 105.33 90 top
PC1119  .1U_0402_16V7K  [C_0402]  111.11 101.99 0 bottom
PC1120  0.022U_0402_25V7K  [C_0402]  120.27 100.47 270 top
PC1121  0.01UF_0402_25V7K  [C_0402]  122.56 108.02 0 top
PC1122  0.022U_0402_25V7K  [C_0402]  110.72 101.99 0 top
PC1123  0.022U_0402_25V7K  [C_0402]  119.39 100.47 270 top
PC1124  0.022U_0402_25V7K  [C_0402]  118.49 100.47 270 top
PC1125  0.022U_0402_25V7K  [C_0402]  110.72 102.94 0 top
PC1126  .1U_0402_16V7K  [C_0402]  118.68 98.18 270 top
PC1127  .047U_0402_16V7K  [C_0402]  119.64 98.18 270 top
PC1128  2200P_0402_50V7K  [C_0402]  119.44 100.47 270 bottom
PC1129  330P_0402_50V7K  [C_0402]  113.86 100.47 270 top
PC1130  470P_0402_50V7K  [C_0402]  116.59 97.8 90 bottom
PC1131  68P_0402_50V8J  [C_0402]  115.7 100.47 270 top
PC1132  680P_0402_50V7K  [C_0402]  116.59 98.69 270 top
PC1133  0.22U_0402_16V7K  [C_0402]  112.04 103.96 180 bottom
PC1134  8200P_0402_25V7K  [C_0402]  115.63 97.8 90 bottom
PC1135  0.22U_0402_16V7K  [C_0402]  118.99 98.14 270 bottom
PC1136  0.1U_0402_25V6  [C_0402]  123.41 108.14 180 bottom
PC1137  0.1U_0402_10V7K  [C_0402]  113.93 114.05 180 top
PC1138  470P_0402_50V7K  [C_0402]  109.55 108.09 180 top
PC1139  1000P_0402_50V7K  [C_0402]  111.13 108.09 0 bottom
PC1200  4.7U_0402_6.3V6M  [C_0402]  137.61 107.45 90 bottom
PC1201  0.1U_0402_25V6  [C_0402]  137.54 111.06 90 bottom
PC1207  470U_D2_2VM_R4.5M~D  [C_D2]  158.46 97.93 180 bottom
PC1208  470U_D2_2VM_R4.5M~D  [C_D2]  163.36 97.93 0 bottom
PC1209  47P_0603_50V8J  [C_0603]  149.54 101.35 0 top
PC1210  100U_D_20VM_R55M  [C_D]  134.75 111.71 90 bottom
PC1211  10U_0805_25VAK  [C_0805]  139.6 112.16 0 top
PC1212  10U_0805_25VAK  [C_0805]  139.57 112.15 0 bottom
PC1213  0.1U_0402_25V6  [C_0402]  142.8 105.37 0 bottom
PC1214  2200P_0402_50V7K  [C_0402]  142.77 106.26 0 bottom
PC1220  22U_0603_6.3V6M  [C_0603]  169.28 71.51 180 top
PC1221  1U_0402_6.3V6K  [C_0402]  169.79 69.43 180 top
PC1222  1U_0402_6.3V6K  [C_0402]  169.78 70.37 180 top
PC1223  1U_0402_6.3V6K  [C_0402]  166.55 69.22 0 top
PC1224  1U_0402_6.3V6K  [C_0402]  166.35 79.13 0 top
PC1225  1U_0402_6.3V6K  [C_0402]  166.35 80.02 0 top
PC1226  1U_0402_6.3V6K  [C_0402]  164.45 78.75 0 top
PC1227  4.7U_0402_6.3V6M  [C_0402]  137.73 112.91 90 bottom
PC1228  0.1U_0402_25V6  [C_0402]  137.67 116.52 90 bottom
PC1229  .1U_0402_16V7K  [C_0402]  162.61 79.64 0 top
PC1230  .1U_0402_16V7K  [C_0402]  162.61 78.75 0 top
PC1231  .1U_0402_16V7K  [C_0402]  168.13 79.13 0 top
PC1232  .1U_0402_16V7K  [C_0402]  160.51 69.16 0 top
PC1233  .1U_0402_16V7K  [C_0402]  167.05 70.37 0 top
PC1234  47P_0603_50V8J  [C_0603]  148.91 116.91 0 bottom
PC1235  10U_0805_25VAK  [C_0805]  139.36 118.63 0 bottom
PC1236  10U_0805_25VAK  [C_0805]  139.4 119.58 0 top
PC1237  0.1U_0402_25V6  [C_0402]  139.8 118.27 0 top
PC1238  2200P_0402_50V7K  [C_0402]  139.83 117.38 0 top
PC1239  .1U_0402_16V7K  [C_0402]  159.78 79.35 180 top
PC1240  .1U_0402_16V7K  [C_0402]  168.13 80.02 0 top
PC1241  .1U_0402_16V7K  [C_0402]  164.45 79.64 0 top
PC1242  .1U_0402_16V7K  [C_0402]  160.7 78.75 0 top
PC1243  .1U_0402_16V7K  [C_0402]  166.16 70.37 180 top
PC1244  .1U_0402_16V7K  [C_0402]  160.7 79.64 0 top
PC1245  .1U_0402_16V7K  [C_0402]  163.27 69.16 180 top
PC1246  .1U_0402_16V7K  [C_0402]  158.86 80.3 0 top
PC1247  .1U_0402_16V7K  [C_0402]  170.12 68.54 180 top
PC1248  .1U_0402_16V7K  [C_0402]  165.34 69.16 180 top
PC1249  4.7U_0402_6.3V6M  [C_0402]  154.36 118.88 0 bottom
PC1250  0.1U_0402_25V6  [C_0402]  158.29 118.75 0 bottom
PC1251  10U_0805_25VAK  [C_0805]  160.34 117.26 270 bottom
PC1252  10U_0805_25VAK  [C_0805]  160.34 117.26 270 top
PC1253  0.1U_0402_25V6  [C_0402]  161.67 117.29 270 top
PC1254  2200P_0402_50V7K  [C_0402]  161.67 117.36 270 bottom
PC1255  47P_0603_50V8J  [C_0603]  161.35 111.32 180 top
PC1256  100U_D_20VM_R55M  [C_D]  129.99 111.71 90 bottom
PC1261  22U_0603_6.3V6M  [C_0603]  160.51 70.3 0 top
PC1262  220U_D7_2VM_R6M  [C_EEFSS0D221R]  163.36 98.37 0 top
PC1263  22U_0603_6.3V6M  [C_0603]  158.42 100.28 0 top
PC1264  22U_0603_6.3V6M  [C_0603]  158.42 99.07 0 top
PC1265  22U_0603_6.3V6M  [C_0603]  158.42 97.86 0 top
PC1269  22U_0603_6.3V6M  [C_0603]  162.93 70.24 0 top
PC1271  22U_0603_6.3V6M  [C_0603]  164.32 71.51 180 top
PC1274  22U_0603_6.3V6M  [C_0603]  158.42 96.66 0 top
PC1276  22U_0603_6.3V6M  [C_0603]  160.45 71.57 0 top
PC1277  1.5P_0402_50V8C  [C_0402]  142.77 106.26 0 top
PC1300  47U_0805_6.3V6M  [C_0805]  152.17 71.95 180 top
PC1301  470U_D2_2VM_R4.5M~D  [C_D2]  117.98 76.4 180 bottom
PC1302  1U_0402_16V6K  [C_0402]  104.14 78.8 90 bottom
PC1303  47U_0805_6.3V6M  [C_0805]  147.43 71.95 0 top
PC1304  47U_0805_6.3V6M  [C_0805]  146.24 71.98 180 top
PC1305  47U_0805_6.3V6M  [C_0805]  146.22 74.18 180 top
PC1306  47U_0805_6.3V6M  [C_0805]  147.62 76.02 0 top
PC1307  470U_D2_2VM_R4.5M~D  [C_D2]  122.68 74.81 270 bottom
PC1308  0.1U_0402_25V6  [C_0402]  104.14 82.36 90 bottom
PC1309  47U_0805_6.3V6M  [C_0805]  123.89 70.46 270 top
PC1310  47U_0805_6.3V6M  [C_0805]  147.56 74.11 0 top
PC1311  47U_0805_6.3V6M  [C_0805]  146.27 76.01 180 top
PC1312  47U_0805_6.3V6M  [C_0805]  122.11 70.46 270 top
PC1313  0.1U_0402_25V6  [C_0402]  113.53 96.15 0 top
PC1314  22U_0603_6.3V6M  [C_0603]  146.92 77.61 0 top
PC1315  10U_0805_25VAK  [C_0805]  107.29 85.16 0 top
PC1316  10U_0805_25VAK  [C_0805]  107.29 85.16 0 bottom
PC1317  2200P_0402_50V7K  [C_0402]  107.37 83.83 0 bottom
PC1318  680P_0603_50V7K  [C_0603]  111.76 77.35 270 top
PC1319  0.1U_0402_25V6  [C_0402]  107.37 83.83 0 top
PC1320  1U_0402_6.3V6K  [C_0402]  156.96 80.35 0 top
PC1321  1U_0402_6.3V6K  [C_0402]  148.64 79.64 0 top
PC1322  1U_0402_6.3V6K  [C_0402]  148.64 78.69 0 top
PC1323  1U_0402_6.3V6K  [C_0402]  155.81 69.17 0 top
PC1324  1U_0402_6.3V6K  [C_0402]  150.73 78.69 0 top
PC1325  1U_0402_6.3V6K  [C_0402]  150.73 79.64 0 top
PC1326  .1U_0402_16V7K  [C_0402]  153.97 69.17 0 top
PC1327  .1U_0402_16V7K  [C_0402]  146.48 79.64 0 top
PC1328  .1U_0402_16V7K  [C_0402]  156.96 79.27 0 top
PC1329  .1U_0402_16V7K  [C_0402]  152.89 79.7 0 top
PC1330  .1U_0402_16V7K  [C_0402]  154.99 78.69 0 top
PC1331  .1U_0402_16V7K  [C_0402]  152.89 78.69 0 top
PC1332  .1U_0402_16V7K  [C_0402]  152.12 69.24 0 top
PC1333  .1U_0402_16V7K  [C_0402]  150.21 69.24 0 top
PC1334  .1U_0402_16V7K  [C_0402]  146.48 78.69 0 top
PC1335  .1U_0402_16V7K  [C_0402]  144.45 78.75 0 top
PC1336  1U_0402_16V6K  [C_0402]  103.68 70.62 0 bottom
PC1337  0.1U_0402_25V6  [C_0402]  104.52 77.17 270 bottom
PC1338  .1U_0402_16V7K  [C_0402]  154.99 79.7 0 top
PC1339  .1U_0402_16V7K  [C_0402]  144.5 69.24 0 top
PC1340  .1U_0402_16V7K  [C_0402]  146.47 69.17 0 top
PC1341  .1U_0402_16V7K  [C_0402]  144.45 79.7 0 top
PC1342  .1U_0402_16V7K  [C_0402]  148.31 69.24 0 top
PC1343  10U_0805_25VAK  [C_0805]  106.69 76.65 0 bottom
PC1344  10U_0805_25VAK  [C_0805]  106.69 76.65 0 top
PC1345  0.1U_0402_25V6  [C_0402]  107.6 77.99 0 bottom
PC1346  2200P_0402_50V7K  [C_0402]  107.6 77.99 0 top
PC1347  680P_0603_50V7K  [C_0603]  111.95 73.48 90 top
PC1348  22U_0603_6.3V6M  [C_0603]  151.88 76.26 180 top
PC1349  22U_0603_6.3V6M  [C_0603]  157.01 76.21 180 top
PC1350  22U_0603_6.3V6M  [C_0603]  153.25 72.21 0 top
PC1351  22U_0603_6.3V6M  [C_0603]  157.01 73.53 180 top
PC1352  22U_0603_6.3V6M  [C_0603]  157.01 74.88 180 top
PC1353  22U_0603_6.3V6M  [C_0603]  153.08 73.54 0 top
PC1354  22U_0603_6.3V6M  [C_0603]  153.08 76.27 0 top
PC1355  0.1U_0402_25V6  [C_0402]  105.8 93.73 180 bottom
PC1356  10U_0805_25VAK  [C_0805]  107.06 95.6 0 top
PC1357  2200P_0402_50V7K  [C_0402]  105.8 93.73 180 top
PC1358  10U_0805_25VAK  [C_0805]  107.06 95.6 0 bottom
PC1359  22U_0603_6.3V6M  [C_0603]  151.89 74.94 180 top
PC1360  22U_0603_6.3V6M  [C_0603]  153.15 74.88 0 top
PC1361  22U_0603_6.3V6M  [C_0603]  151.85 73.55 180 top
PC1362  22U_0603_6.3V6M  [C_0603]  157.01 72.21 180 top
PC1363  22U_0603_6.3V6M  [C_0603]  154.12 70.35 0 top
PC1364  1U_0402_16V6K  [C_0402]  114.75 94.12 180 top
PC1365  680P_0603_50V7K  [C_0603]  105.6 91.19 90 bottom
PC1366  22U_0603_6.3V6M  [C_0603]  121.92 89.1 90 bottom
PC1367  22U_0603_6.3V6M  [C_0603]  123.19 91.84 90 bottom
PC1368  22U_0603_6.3V6M  [C_0603]  121.92 91.84 90 bottom
PC1369  22U_0603_6.3V6M  [C_0603]  120.65 91.84 90 bottom
PC1370  22U_0603_6.3V6M  [C_0603]  123.19 89.1 90 bottom
PC1372  22U_0603_6.3V6M  [C_0603]  151.69 70.37 0 top
PC1373  22U_0603_6.3V6M  [C_0603]  149.27 70.37 0 top
PC1374  22U_0603_6.3V6M  [C_0603]  146.86 70.37 0 top
PC1375  22U_0603_6.3V6M  [C_0603]  154.54 77.54 0 top
PC1376  22U_0603_6.3V6M  [C_0603]  153.42 77.61 180 top
PC1377  22U_0603_6.3V6M  [C_0603]  149.46 77.61 0 top
PC1378  22U_0603_6.3V6M  [C_0603]  144.45 70.37 0 top
PC1379  22U_0603_6.3V6M  [C_0603]  145.91 77.63 180 top
PC1380  22U_0603_6.3V6M  [C_0603]  169.9 93.28 90 bottom
PC1382  47U_0805_6.3V6M  [C_0805]  171.75 76.65 180 top
PC1383  .1U_0402_16V7K  [C_0402]  166.24 93.53 90 bottom
PC1384  .1U_0402_16V7K  [C_0402]  177.23 93.54 90 bottom
PC1385  22U_0603_6.3V6M  [C_0603]  171.75 75.13 180 top
PC1386  22U_0603_6.3V6M  [C_0603]  171.56 79.51 180 top
PC1388  47U_0805_6.3V6M  [C_0805]  116.14 88.3 270 top
PC1389  22U_0603_6.3V6M  [C_0603]  118.94 88.02 270 top
PC1390  22U_0603_6.3V6M  [C_0603]  171.75 73.8 180 top
PC1391  22U_0603_6.3V6M  [C_0603]  117.67 88.02 270 top
PC1393  47U_0805_6.3V6M  [C_0805]  116.33 88.53 270 bottom
PC1394  22U_0603_6.3V6M  [C_0603]  167.39 93.29 90 bottom
PC1395  22U_0603_6.3V6M  [C_0603]  176.15 93.54 90 bottom
PC1396  22U_0603_6.3V6M  [C_0603]  168.59 93.26 90 bottom
PC1397  220U_D7_2VM_R6M  [C_EEFSS0D221R]  161.14 75.57 0 top
PD100  AZ5125-01H.R7G_SOD523-2  [AZ5125-01HPR7G_SOD523-2]  17.83 76.84 180 top
PD101  -  [TVNST52302AB0_SOT523-3]  21.71 12.57 180 top
PD102  -  [TVNST52302AB0_SOT523-3]  18.3 10.93 180 top
PD201  -  [SDMK0340L-7-F_SOD323-2]  4.82 17.28 180 bottom
PD202  -  [SDMK0340L-7-F_SOD323-2]  31.05 24.27 0 top
PD203  -  [SDMK0340L-7-F_SOD323-2]  15.47 2.27 180 top
PD204  -  [BAT54CW_SOT323-3]  26.21 1.76 180 top
PD205  -  [SDMK0340L-7-F_SOD323-2]  24.96 30.68 0 top
PD207  -  [SDMK0340L-7-F_SOD323-2]  21.13 6.89 180 top
PD211  -  [SDMK0340L-7-F_SOD323-2]  4.82 14.99 180 bottom
PD301  -  [SX34H_SMA2]  27.69 24.77 180 bottom
PD302  -  [SDMK0340L-7-F_SOD323-2]  51.12 17.86 90 bottom
PD303  -  [SDMK0340L-7-F_SOD323-2]  57.34 9.15 180 top
PD304  -  [SDMK0340L-7-F_SOD323-2]  57.34 9.15 270 bottom
PH1100  470K_0402_5%_ TSM0B474J4702RE  [R_0402]  105.16 84.86 270 bottom
PH1101  10K_0402_5%_B25/50 4250K  [R_0402]  114.64 91.68 180 bottom
PH1102  10K_0402_5%_B25/50 4250K  [R_0402]  121.22 85.42 180 bottom
PH1103  10K_0402_5%_B25/50 4250K  [R_0402]  149.2 100.88 0 bottom
PH1104  470K_0402_5%_ TSM0B474J4702RE  [R_0402]  143.78 104.4 180 bottom
PJP300  PAD-OPEN1x1m  [JUMP_43X39]  55.06 18.6 90 bottom
PJP400  -  [JUMP_43X118]  318.58 10.8 0 top
PJP402  PAD-OPEN 4x4m  [JUMP_43X118]  324.68 23.38 180 top
PJP403  PAD-OPEN 4x4m  [JUMP_43X118]  323.41 5.34 180 top
PJP500  -  [JUMP_43X118]  119.51 8.35 90 bottom
PJP600  -  [JUMP_43X118]  279.59 30.74 180 bottom
PJP601  PAD-OPEN1x1m  [JUMP_43X39]  283.15 30.43 0 bottom
PJP602  PAD-OPEN 3x3m  [JUMP_43X79]  283.02 28.9 270 top
PJP603  PAD-OPEN 4x4m  [JUMP_43X118]  256.73 25.2 270 bottom
PJP700  PAD-OPEN 3x3m  [JUMP_43X79]  236.86 45.32 90 top
PJP701  PAD-OPEN 4x4m  [JUMP_43X118]  241.05 63.2 270 bottom
PJP702  PAD-OPEN 4x4m  [JUMP_43X118]  241.72 61.48 180 top
PJP800  -  [JUMP_43X118]  117.22 63.83 0 bottom
PJP900  -  [JUMP_43X118]  209.87 58.01 90 top
PJP1200  -  [JUMP_43X118]  129.8 107.13 90 bottom
PJP1205  PAD-OPEN1x1m  [JUMP_43X39]  306.78 22.87 180 top
PJP1206  PAD-OPEN1x1m  [JUMP_43X39]  276.28 8.64 0 top
PJP1300  -  [JUMP_43X118]  107.25 68.59 270 top
PJP1301  -  [JUMP_43X118]  109.28 97.86 90 bottom
PJP1302  PAD-OPEN 43x39  [JUMP_43X39]  103.07 17.92 180 top
PJP1303  PAD-OPEN 43x39  [JUMP_43X39]  102.95 13.6 180 top
PL104  BLM15AG102SN1D_2P  [MURAT_BLM15AG102SN1D_2P]  17.82 77.99 180 top
PL105  HCB2012KF-121T50_0805  [TAI-T_HCB2012KF-121T50_2P]  26.54 77.03 0 bottom
PL106  HCB2012KF-121T50_0805  [TAI-T_HCB2012KF-121T50_2P]  27.1 78.62 90 bottom
PL107  HCB2012KF-121T50_0805  [TAI-T_HCB2012KF-121T50_2P]  23.37 21.98 270 bottom
PL108  HCB2012KF-121T50_0805  [TAI-T_HCB2012KF-121T50_2P]  21.59 21.98 270 bottom
PL200  HCB2012KF-121T50_0805  [TAI-T_HCB2012KF-121T50_2P]  26.39 69.7 90 top
PL201  HCB2012KF-121T50_0805  [TAI-T_HCB2012KF-121T50_2P]  26.39 69.7 90 bottom
PL202  HCB2012KF-121T50_0805  [TAI-T_HCB2012KF-121T50_2P]  28.46 62.81 270 bottom
PL203  HCB2012KF-121T50_0805  [TAI-T_HCB2012KF-121T50_2P]  27.75 62.81 270 top
PL300  HCB2012KF-121T50_0805  [TAI-T_HCB2012KF-121T50_2P]  52.44 9.72 180 bottom
PL301  HCB2012KF-121T50_0805  [TAI-T_HCB2012KF-121T50_2P]  52.44 8.01 180 bottom
PL302  3.3UH_PIMB104T-3R3MS_10A_20%  [CYNTE_PIMB104T-3R3MS_2P]  36.45 3.97 90 bottom
PL400  3.3UH_6.3A_20%_7X7X3_M  [L_7X7X3_M_2P]  331.37 25.28 0 top
PL401  1.5UH_ETQP3W1R5WFN_9.5A_20%  [PANAS_ETQP3W1R5WFN_2P]  336.13 6.1 180 top
PL402  HCB2012KF-121T50_0805  [TAI-T_HCB2012KF-121T50_2P]  318.26 14.42 0 top
PL403  HCB2012KF-121T50_0805  [TAI-T_HCB2012KF-121T50_2P]  318.26 16.2 0 top
PL500  HCB2012KF-121T50_0805  [TAI-T_HCB2012KF-121T50_2P]  136.65 8.76 270 bottom
PL501  1UH_6.6A_20%_5X5X3_M  [L_5X5X3_M_2P]  128.4 3.63 180 bottom
PL600  1UH_11A_20%_7X7X3_M  [L_7X7X3_M_2P]  262.53 31.76 0 bottom
PL601  HCB2012KF-121T50_0805  [TAI-T_HCB2012KF-121T50_2P]  279.39 27.31 180 bottom
PL700  0.68UH_PCMC063T-R68MN_15.5A_20%  [PANAS_ETQP3W1R5WFN_2P]  242.01 57.16 0 bottom
PL701  HCB2012KF-121T50_0805  [TAI-T_HCB2012KF-121T50_2P]  239.65 44.87 90 top
PL800  HCB2012KF-121T50_0805  [TAI-T_HCB2012KF-121T50_2P]  105.35 57.48 90 bottom
PL801  1UH_6.6A_20%_5X5X3_M  [L_5X5X3_M_2P]  112.9 60.52 90 bottom
PL900  HCB2012KF-121T50_0805  [TAI-T_HCB2012KF-121T50_2P]  213.23 48.97 0 top
PL901  1UH_6.6A_20%_5X5X3_M  [L_5X5X3_M_2P]  217.81 56.46 180 bottom
PL1000  0.22UH_24A_+-20%_7X7X4_M  [L_7X7X4_M_2P]  183.46 107.26 0 bottom
PL1001  0.22UH_24A_+-20%_7X7X4_M  [L_7X7X4_M_2P]  183.65 115.83 0 bottom
PL1002  0.22UH_24A_+-20%_7X7X4_M  [L_7X7X4_M_2P]  183.53 99.7 0 bottom
PL1003  HCB2012KF-121T50_0805  [TAI-T_HCB2012KF-121T50_2P]  171.15 117.8 0 bottom
PL1004  HCB2012KF-121T50_0805  [TAI-T_HCB2012KF-121T50_2P]  171.15 116.02 0 bottom
PL1200  0.22UH_24A_+-20%_7X7X4_M  [L_7X7X4_M_2P]  146.46 105.16 0 bottom
PL1201  0.22UH_24A_+-20%_7X7X4_M  [L_7X7X4_M_2P]  146.46 112.53 0 bottom
PL1202  0.22UH_24A_+-20%_7X7X4_M  [L_7X7X4_M_2P]  158.24 108.67 270 bottom
PL1203  HCB2012KF-121T50_0805  [TAI-T_HCB2012KF-121T50_2P]  135.13 106.88 90 bottom
PL1204  HCB2012KF-121T50_0805  [TAI-T_HCB2012KF-121T50_2P]  133.41 106.88 90 bottom
PL1300  0.22UH_24A_+-20%_7X7X4_M  [L_7X7X4_M_2P]  112.98 82.43 0 bottom
PL1301  0.22UH_24A_+-20%_7X7X4_M  [L_7X7X4_M_2P]  112.09 70.37 0 bottom
PL1303  HCB2012KF-121T50_0805  [TAI-T_HCB2012KF-121T50_2P]  106.62 67.06 90 bottom
PL1304  HCB2012KF-121T50_0805  [TAI-T_HCB2012KF-121T50_2P]  108.4 67.06 90 bottom
PL1305  HCB2012KF-121T50_0805  [TAI-T_HCB2012KF-121T50_2P]  105.6 97.04 270 bottom
PL1306  0.47UH_PCMB053T-R47MS_12A_20%  [CYNTE_PCMB053T-R47MS_2P]  108.4 88.64 0 bottom
PQ100  -  [FDV301N-G_SOT23-3]  42.74 33.98 180 top
PQ101  -  [MMBT3904WH_SOT323-3]  39.03 32.77 270 top
PQ103  -  [L2N7002WT1G_SC70-3]  61.97 19.38 90 bottom
PQ200  -  [AON7409_DFN8-5]  14.86 68.65 0 bottom
PQ201  -  [AON7409_DFN8-5]  20.51 65.79 180 bottom
PQ202  -  [AON7409_DFN8-5]  29.49 11.67 270 top
PQ203  -  [AON7409_DFN8-5]  27.43 11.57 180 top
PQ204  -  [NTR4502PT1G_SOT23-3]  21.46 94.22 180 bottom
PQ205  S TR 2N7002KW 1N SOT323-3  [SSM3K7002FU_SC70-3]  19.63 100.34 90 bottom
PQ206  S TR 2N7002KW 1N SOT323-3  [SSM3K7002FU_SC70-3]  25.08 100.32 0 bottom
PQ207  S TR 2N7002KW 1N SOT323-3  [SSM3K7002FU_SC70-3]  32.45 6.68 90 top
PQ208  S TR 2N7002KW 1N SOT323-3  [SSM3K7002FU_SC70-3]  20.32 90.37 180 bottom
PQ209  S TR 2N7002KW 1N SOT323-3  [SSM3K7002FU_SC70-3]  28.64 4.77 180 top
PQ210  S TR 2N7002KW 1N SOT323-3  [SSM3K7002FU_SC70-3]  31.05 4.77 180 top
PQ211  S TR 2N7002KW 1N SOT323-3  [SSM3K7002FU_SC70-3]  22.73 90.37 180 bottom
PQ212  -  [AON7409_DFN8-5]  23.84 58.58 90 bottom
PQ213  -  [AON7409_DFN8-5]  23.37 65.22 0 bottom
PQ214  -  [AON7409_DFN8-5]  18.45 62.73 270 bottom
PQ215  -  [NTR4502PT1G_SOT23-3]  16.6 6.89 90 top
PQ216  -  [NTR4502PT1G_SOT23-3]  24.94 60.55 0 top
PQ217  -  [NTR4502PT1G_SOT23-3]  26.07 87.92 180 bottom
PQ218  S TR 2N7002KW 1N SOT323-3  [SSM3K7002FU_SC70-3]  17.63 49.51 0 bottom
PQ219  S TR 2N7002KW 1N SOT323-3  [SSM3K7002FU_SC70-3]  27.75 93.1 180 bottom
PQ220  S TR 2N7002KW 1N SOT323-3  [SSM3K7002FU_SC70-3]  22.18 54.12 270 bottom
PQ221  -  [AO3413_SOT23-3]  36.32 24.88 0 top
PQ222  S TR 2N7002KW 1N SOT323-3  [SSM3K7002FU_SC70-3]  25.27 93.1 180 bottom
PQ223  S TR 2N7002KW 1N SOT323-3  [SSM3K7002FU_SC70-3]  24.57 53.11 90 bottom
PQ224  -  [AO3413_SOT23-3]  21.97 15.86 0 top
PQ225  S TR 2N7002KW 1N SOT323-3  [SSM3K7002FU_SC70-3]  28.19 24.14 90 top
PQ226  S TR 2N7002KW 1N SOT323-3  [SSM3K7002FU_SC70-3]  28.58 28.21 180 top
PQ227  S TR 2N7002KW 1N SOT323-3  [SSM3K7002FU_SC70-3]  7.43 17.79 0 bottom
PQ228  S TR 2N7002KW 1N SOT323-3  [SSM3K7002FU_SC70-3]  10.15 24.13 270 bottom
PQ229  S TR 2N7002KW 1N SOT323-3  [SSM3K7002FU_SC70-3]  23.87 28.71 90 top
PQ230  S TR 2N7002KW 1N SOT323-3  [SSM3K7002FU_SC70-3]  7.68 21.09 0 bottom
PQ231  S TR 2N7002KW 1N SOT323-3  [SSM3K7002FU_SC70-3]  32.79 30.93 180 top
PQ232  S TR 2N7002KW 1N SOT323-3  [SSM3K7002FU_SC70-3]  27.5 96.89 180 bottom
PQ233  S TR 2N7002KW 1N SOT323-3  [SSM3K7002FU_SC70-3]  16.38 24.71 180 top
PQ234  S TR 2N7002KW 1N SOT323-3  [SSM3K7002FU_SC70-3]  22.99 9.28 90 top
PQ300  -  [SIR472DP-T1-GE3_POWERPAK8-5]  42.67 13.85 90 bottom
PQ301  -  [SIR472DP-T1-GE3_POWERPAK8-5]  42.51 8.02 90 bottom
PQ302  -  [SIRA06DP-T1-GE_POWERPAKSO-8-5]  47.88 5.98 270 bottom
PQ303  -  [AON7409_DFN8-5]  28.13 22.16 270 bottom
PQ304  S TR 2N7002KW 1N SOT323-3  [SSM3K7002FU_SC70-3]  57.42 10.98 180 bottom
PQ400  -  [MDV1528URH_PDFN33-8-5]  332.42 21.15 180 top
PQ401  -  [MDU1516URH_POWERDFN56-8-5]  327.34 10.49 0 top
PQ402  -  [MDV1524URH_PDFN33-8-5]  334.58 18.11 0 top
PQ403  -  [MDU1512RH_POWERDFN56-8-5]  337.12 15.82 180 top
PQ600  -  [MDV1527URH_POWERDFN33-8-5]  271 30.91 90 bottom
PQ601  -  [MDV1522URH_PDFN33-8-5]  273.57 28.29 270 bottom
PQ1000  -  [CSD87351Q5D_SON8-7]  175.36 107.83 90 bottom
PQ1001  -  [CSD87351Q5D_SON8-7]  175.55 115.26 90 bottom
PQ1002  -  [CSD87351Q5D_SON8-7]  175.3 100.34 90 bottom
PQ1300  -  [AON7934_DFN3X3A8-10]  107.13 91.96 90 bottom
PQ1301  -  [AON7409_DFN8-5]  32.36 13.56 90 top
PR21  44.2_0402_1%  [R_0402]  17.73 56.37 180 bottom
PR27  0_0402_5%  [R_0402]  26.86 25.74 90 top
PR100  0_0402_5%  [R_0402]  45.15 33.68 270 top
PR101  2.2K_0402_1%  [R_0402]  46.1 31.84 270 top
PR102  33_0402_5%  [R_0402]  45.15 31.84 270 top
PR103  100K_0402_1%  [R_0402]  40.34 34.45 180 top
PR104  10K_0402_1%  [R_0402]  40.26 31.43 90 top
PR105  15K_0402_1%  [R_0402]  38.5 34.45 180 top
PR106  100_0402_1%  [R_0402]  19.43 17.2 90 top
PR107  1M_0402_5%  [R_0402]  63.18 18.36 270 bottom
PR108  100_0402_1%  [R_0402]  18.92 15.17 90 top
PR109  100K_0402_1%  [R_0402]  65.22 12.38 90 bottom
PR110  37.4K_0402_1%  [R_0402]  62.29 18.37 270 bottom
PR111  100_0402_1%  [R_0402]  19.75 13.04 270 top
PR112  10K_0402_1%  [R_0402]  19.75 11.18 270 top
PR113  0_0402_5%  [R0402_0OHM]  65.22 14.16 90 bottom
PR200  100K_0402_5%  [R_0402]  18.73 64.3 180 bottom
PR201  1M_0402_5%  [R_0402]  20.26 88.34 180 bottom
PR202  100K_0402_5%  [R_0402]  20.24 98.05 0 bottom
PR203  100K_0402_5%  [R_0402]  16.97 64.3 180 bottom
PR204  1M_0402_5%  [R_0402]  26.23 14.55 180 top
PR205  1M_0402_5%  [R_0402]  19.37 89.23 0 bottom
PR206  100K_0402_5%  [R_0402]  22.15 98.05 0 bottom
PR207  0_0402_5%  [R_0402]  24.51 53.27 90 top
PR208  0_0402_5%  [R_0402]  26.94 56.37 180 top
PR209  0_0402_5%  [R_0402]  22.78 102.55 180 bottom
PR210  22K_0402_5%  [R_0402]  29.9 8.33 0 top
PR211  0_0402_5%  [R_0402]  16.82 55.48 0 bottom
PR212  0_0402_5%  [R_0402]  29.34 7.26 270 top
PR213  1M_0402_5%  [R_0402]  22.14 87.06 0 bottom
PR214  0_0402_5%  [R_0402]  30.52 1.71 0 top
PR215  0.01_1206_1%  [R_1206_4P-D]  20.44 63.19 270 bottom
PR216  0.01_1206_1%  [R_1206_4P-D]  22.05 67.8 0 bottom
PR217  1M_0402_5%  [R_0402]  23.24 88.32 90 bottom
PR218  0_0402_5%  [R_0402]  11.52 3.87 90 top
PR219  1M_0402_5%  [R_0402]  18.59 58.28 180 bottom
PR220  100K_0402_5%  [R_0402]  22.48 56.03 270 bottom
PR221  0_0402_5%  [R_0402]  10.59 3.87 90 top
PR222  1M_0402_5%  [R_0402]  25.22 56.07 0 bottom
PR223  100K_0402_5%  [R_0402]  27.43 91.83 180 bottom
PR224  1M_0402_5%  [R_0402]  26.67 85.16 90 bottom
PR225  1M_0402_5%  [R_0402]  17.68 57.42 0 bottom
PR226  100K_0402_5%  [R_0402]  27.62 85.16 90 bottom
PR227  0_0402_5%  [R_0402]  26.58 64.31 90 top
PR228  0_0402_5%  [R_0402]  24.64 97.24 270 bottom
PR229  100K_0402_5%  [R_0402]  23.34 54.78 270 bottom
PR230  100K_0402_5%  [R_0402]  25.59 91.83 180 bottom
PR231  100K_0402_1%  [R_0402]  27.08 55.75 270 bottom
PR232  10K_0402_1%  [R_0402]  26.14 55.18 180 bottom
PR233  0_0402_5%  [R_0402]  16.83 58.29 270 bottom
PR234  100K_0402_5%  [R_0402]  21.28 52.49 180 bottom
PR235  0_0402_5%  [R_0402]  28.26 100.11 180 bottom
PR236  221K_0402_1%~D  [R_0402]  26.59 31.98 0 top
PR237  100K_0402_5%  [R_0402]  11.74 7.4 270 top
PR238  100K_0402_1%  [R_0402]  25.71 28.38 0 top
PR239  1.8M_0402_1%  [R_0402]  29.8 30.36 180 top
PR240  100K_0402_5%  [R_0402]  15.58 4.42 0 top
PR241  100K_0402_1%  [R_0402]  25.97 25.74 90 top
PR242  100K_0402_1%  [R_0402]  23.86 30.36 0 bottom
PR243  100K_0402_5%  [R_0402]  13.79 4.42 0 top
PR244  100K_0402_5%  [R_0402]  12.69 6.49 90 top
PR245  130K_0402_1%  [R_0402]  25.71 27.5 0 top
PR246  0_1206_5%  [R_1206]  23.26 7.4 270 top
PR247  1.8M_0402_1%  [R_0402]  25.02 26.65 270 top
PR248  150K_0402_1%  [R_0402]  24 26.5 270 top
PR249  100K_0402_1%  [R_0402]  22.24 26.68 180 bottom
PR250  200K_0402_1%  [R_0402]  21.65 27.95 0 bottom
PR251  100K_0402_1%  [R_0402]  9.46 21.6 0 bottom
PR252  100K_0402_1%  [R_0402]  8.48 22.64 90 top
PR253  100K_0402_1%  [R_0402]  9.46 22.49 0 bottom
PR254  180K_0402_1%  [R_0402]  15.36 22.88 0 bottom
PR255  100K_0402_1%  [R_0402]  18.59 22.88 180 bottom
PR256  120K_0402_1%  [R_0402]  25.71 29.27 0 top
PR257  180K_0402_1%  [R_0402]  10.38 23.85 180 top
PR258  1.8M_0402_1%  [R_0402]  17.65 21.01 90 bottom
PR259  1.8M_0402_1%  [R_0402]  10.35 22.79 270 top
PR260  130K_0402_1%  [R_0402]  19.51 19.06 180 bottom
PR261  140K_0402_1%  [R_0402]  9.4 18.61 0 bottom
PR262  0_0402_5%  [R_0402]  25.81 4.64 0 top
PR263  16.5K_0402_1%  [R_0402]  9.46 22.79 270 top
PR264  200K_0402_1%  [R_0402]  9.46 24.77 0 top
PR265  200K_0402_1%  [R_0402]  13.53 22.88 0 bottom
PR266  0_0402_5%  [R_0402]  24.54 3.65 270 top
PR267  0_0402_5%  [R_0402]  25.66 97.24 270 bottom
